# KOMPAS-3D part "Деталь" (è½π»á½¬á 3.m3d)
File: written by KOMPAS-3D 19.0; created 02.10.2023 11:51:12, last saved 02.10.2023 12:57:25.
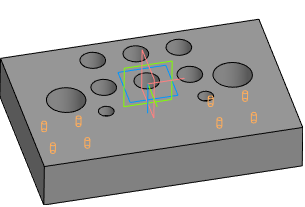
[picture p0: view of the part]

Document properties: Автор: admin; Организация: Hewlett-Packard Company; Полное имя файла: C:\Users\Petrenko-VE\Documents\Клупалка_3.m3d

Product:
- Part/product: Деталь
    Масса: 17.2093

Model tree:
1. Эскиз:1
2. Элемент выдавливания:1
     Расстояние 1 = 50
3. Эскиз:2  (with: Элемент выдавливания:1)
4. Элемент выдавливания:2
     Расстояние 2 = 50
5. Эскиз:3  (with: Элемент выдавливания:1, Элемент выдавливания:2)
6. Элемент выдавливания:3
     Расстояние 2 = 30
7. Условное изображение резьбы:1  (with: Элемент выдавливания:3)  (labels: M5; cil0_24705-2004 coarse)
     Длина резьбы = 10; Шаг резьбы = 0.8; Номинальный диаметр резьбы = 5
8. Подгонка:1  (with: Элемент выдавливания:3)
9. Условное изображение резьбы:2  (with: Элемент выдавливания:3)  (labels: M5; cil0_24705-2004 coarse)
     Длина резьбы = 10; Шаг резьбы = 0.8; Номинальный диаметр резьбы = 5
10. Подгонка:2  (with: Элемент выдавливания:3)
11. Условное изображение резьбы:3  (with: Элемент выдавливания:3)  (labels: M5; cil0_24705-2004 coarse)
     Длина резьбы = 10; Шаг резьбы = 0.8; Номинальный диаметр резьбы = 5
12. Подгонка:3  (with: Элемент выдавливания:3)
13. Условное изображение резьбы:4  (with: Элемент выдавливания:3)  (labels: M5; cil0_24705-2004 coarse)
     Длина резьбы = 10; Шаг резьбы = 0.8; Номинальный диаметр резьбы = 5
14. Подгонка:4  (with: Элемент выдавливания:3)
15. Условное изображение резьбы:5  (with: Элемент выдавливания:3)  (labels: M5; cil0_24705-2004 coarse)
     Длина резьбы = 10; Шаг резьбы = 0.8; Номинальный диаметр резьбы = 5
16. Подгонка:5  (with: Элемент выдавливания:3)
17. Условное изображение резьбы:6  (with: Элемент выдавливания:3)  (labels: M5; cil0_24705-2004 coarse)
     Длина резьбы = 10; Шаг резьбы = 0.8; Номинальный диаметр резьбы = 5
18. Подгонка:6  (with: Элемент выдавливания:3)
19. Условное изображение резьбы:7  (with: Элемент выдавливания:3)  (labels: M5; cil0_24705-2004 coarse)
     Длина резьбы = 10; Шаг резьбы = 0.8; Номинальный диаметр резьбы = 5
20. Подгонка:7  (with: Элемент выдавливания:3)
21. Условное изображение резьбы:8  (with: Элемент выдавливания:3)  (labels: M5; cil0_24705-2004 coarse)
     Длина резьбы = 10; Шаг резьбы = 0.8; Номинальный диаметр резьбы = 5
22. Подгонка:8  (with: Элемент выдавливания:3)
23. Эскиз:4  (with: Элемент выдавливания:1)
24. Элемент выдавливания:4
     Расстояние 2 = 50
25. Эскиз:5  (with: Элемент выдавливания:1, Элемент выдавливания:4)
26. Элемент выдавливания:5
     Расстояние 2 = 21
27. Эскиз:6  (with: Элемент выдавливания:1, Элемент выдавливания:4)
28. Элемент выдавливания:6
     Расстояние 2 = 12
29. Эскиз:7  (with: Элемент выдавливания:1)
30. Элемент выдавливания:7
     Расстояние 2 = 50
